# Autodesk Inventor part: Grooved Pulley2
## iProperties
Created: 2011-05
Part Number: Grooved Pulley2
Material: Steel
Document SubType Name: Modeling
Designer: 904Chiaki
Density: 1 g/cm^3
CustomPartVersion: 1
Author: 904Chiaki
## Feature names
1. Body [Revolution]
2. Groove [Revolution]
3. Fillet External
4. Fillet Internal
5. Groove Pattern [Rectangular Pattern]
6. Extrusion1
7. Extrusion2
8. Mirror1
9. Extrusion3
10. Fillet3
11. Fillet4
12. Extrusion4
13. Fillet5
14. Fillet6
15. Chamfer1
